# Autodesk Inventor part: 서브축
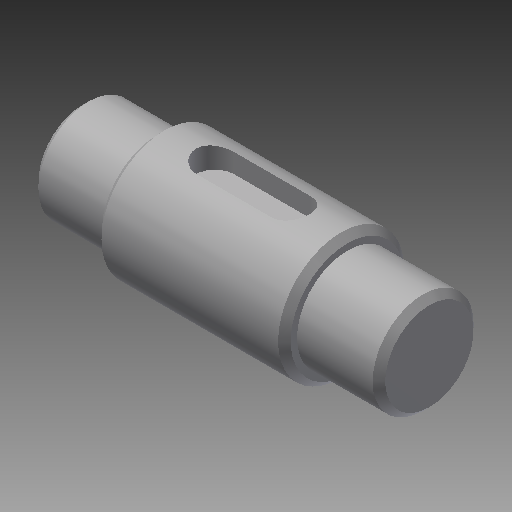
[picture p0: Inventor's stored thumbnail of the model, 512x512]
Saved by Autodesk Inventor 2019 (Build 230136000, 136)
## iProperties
Created: 2019-03
Part Number: 서브축
Material: 강철, 연강
Document SubType Name: Modeling
Designer: mduedu
Density: 1 g/cm^3
Appearance: 강철
Author: mduedu
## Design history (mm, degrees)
sketch "스케치1"
  geometry: L1 (0, 0)-(12, 0); L2 (12, 0)-(12, 8); L3 (12, 8)-(0, 8); L4 (0, 8)-(0, 0); L5 (12, 0)-(42, 0); L6 (42, 0)-(42, 10); L7 (42, 10)-(12, 10); L8 (12, 10)-(12, 0); L9 (42, 0)-(55, 0); L10 (55, 0)-(55, 8); L11 (55, 8)-(42, 8); L12 (42, 8)-(42, 0)
  constraints: 24 end point, 6 parallel, 3 horizontal, 3 perpendicular
  dimensions: "d0" = 16 diameter of L3 L1; "d2" = 20 diameter of L7 L5; "d3" = 16 diameter of L11 L9; "d4" = 12 distance of L2.end L3.end; "d5" = 30 distance of L6.end L7.end; "d6" = 55 distance between parallel lines of L10 L4
revolve "회전1" sketch "스케치1" stored, may be unused: angle "d7" = 90 deg
node "작업 평면1"
sketch "스케치2" dims "d10" = 18
  geometry: L1 (6, -3)-(-6, -3); L2 (-6, -3)-(-6, 3); L3 (-6, 3)-(6, 3); L4 (6, 3)-(6, -3); L5 (15, 10)-(15, -10) reference; 3 further points
  constraints: 8 end point, 2 midpoint, 2 parallel, 2 vertical alignment, 1 horizontal, 1 horizontal alignment, 1 perpendicular, 4 other
  dimensions: "d8" = 6 distance between parallel lines of L3 L1; "d11" = 6 dimension on L5
extrude "돌출1" cut sketch "스케치2" distance "d12" = 3.5; taper "d13" = 0 deg
chamfer "모따기1" distance "d14" = 1; stored, may be unused: second distance "d15" = 2, angle "d16" = 45 deg
chamfer "모따기2" distance "d17" = 1; stored, may be unused: second distance "d18" = 2, angle "d19" = 45 deg
node "솔리드1"
